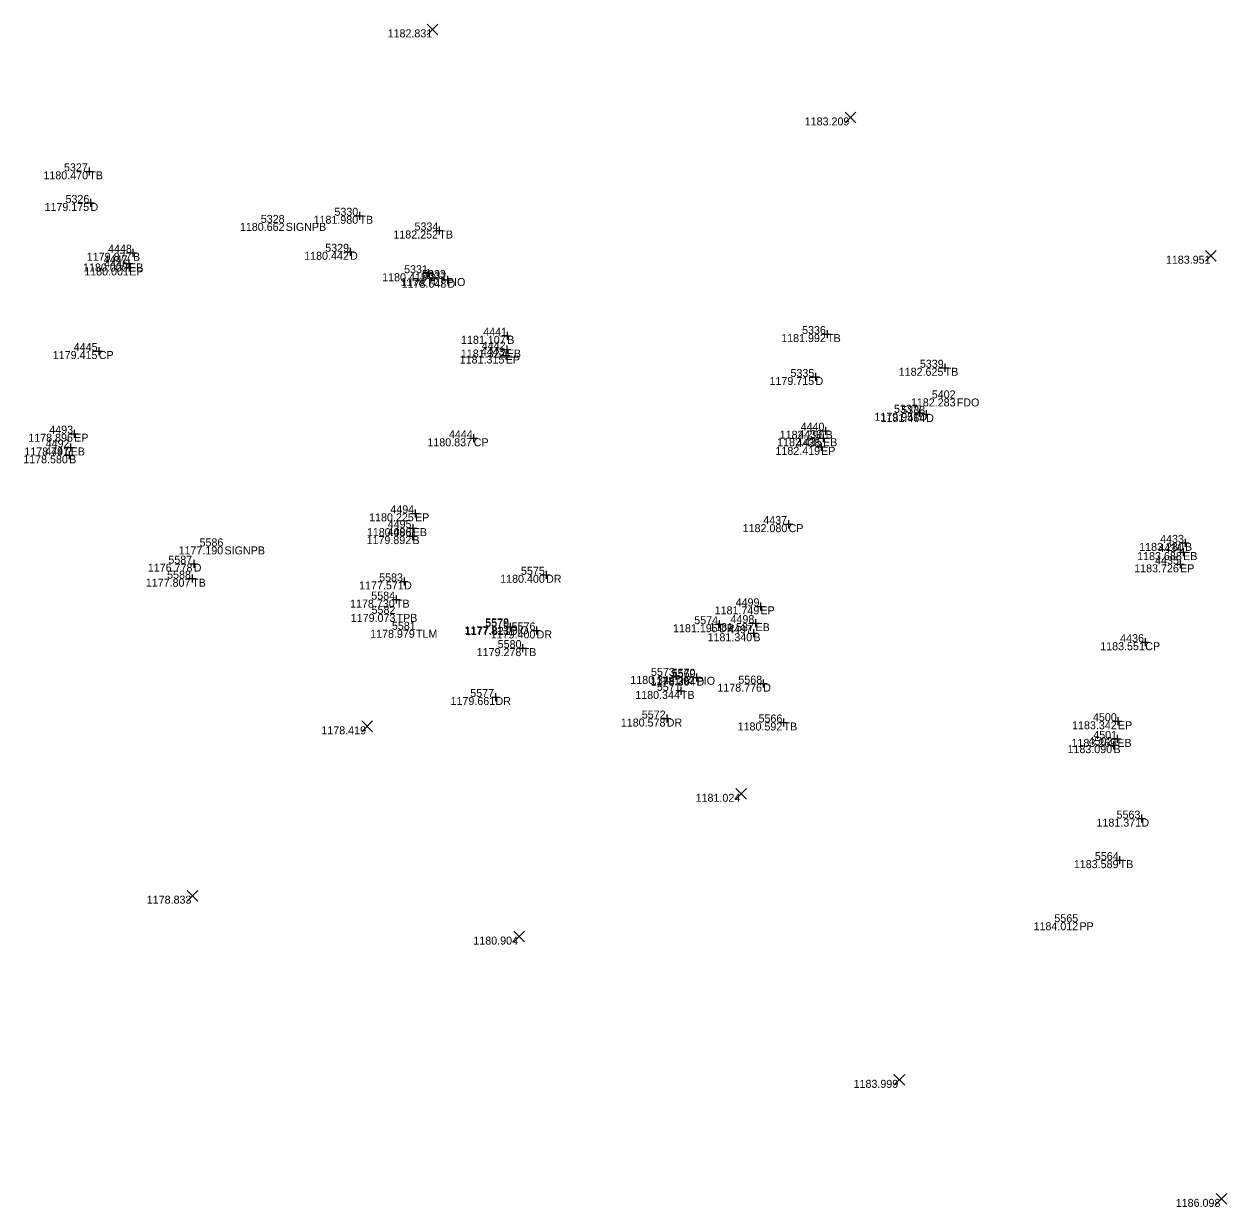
# Model space of a CAD drawing. Extents: x 2044997 to 2050342, y 455233 to 458054.
# Drawn here: x 2046906.2 to 2047056.5, y 457146.9 to 457294.7 of the extents above; entities that cross this region are included whole.
import ezdxf

# ---------------------------------------------------------------- set-up
doc = ezdxf.new("R2010")
doc.units = 0
for name, color, linetype in [('SV_X_Random_Point', 7, 'Continuous'), ('SV_X_Shot_Marker', 7, 'Continuous'), ('SV_X_Text_Comment', 7, 'Continuous'), ('SV_X_Text_Elevation', 7, 'Continuous'), ('SV_X_Text_Name', 7, 'Continuous')]:
    doc.layers.add(name, color=color, linetype=linetype)

msp = doc.modelspace()

# ---------------------------------------------------------------- linework, layer by layer
at = {"layer": 'SV_X_Random_Point'}
for p, q in [((2046956.58, 457293.4), (2046957.92, 457294.74)), ((2046956.58, 457294.74), (2046957.92, 457293.4)), ((2047008.79, 457282.4), (2047010.12, 457283.74)), ((2047008.79, 457283.74), (2047010.12, 457282.4)), ((2047053.8, 457265.12), (2047055.13, 457266.46)), ((2047053.8, 457266.46), (2047055.13, 457265.12)), ((2046948.42, 457206.32), (2046949.75, 457207.66)), ((2046948.42, 457207.66), (2046949.75, 457206.32)), ((2046995.15, 457197.89), (2046996.48, 457199.22)), ((2046995.15, 457199.22), (2046996.48, 457197.89)), ((2046926.62, 457185.16), (2046927.95, 457186.49)), ((2046926.62, 457186.49), (2046927.95, 457185.16)), ((2046967.39, 457180.05), (2046968.72, 457181.39)), ((2046967.39, 457181.39), (2046968.72, 457180.05)), ((2047014.89, 457162.15), (2047016.23, 457163.48)), ((2047014.89, 457163.48), (2047016.23, 457162.15)), ((2047055.14, 457147.28), (2047056.48, 457148.62)), ((2047055.14, 457148.62), (2047056.48, 457147.28))]:
    msp.add_line(p, q, dxfattribs=at)
at = {"layer": 'SV_X_Shot_Marker'}
for p, q in [((2046913.88, 457276.33), (2046914.88, 457276.33)), ((2046914.38, 457276.83), (2046914.38, 457275.83)), ((2046914.38, 457276.33), (2046914.38, 457276.33)), ((2046914.53, 457272.88), (2046914.53, 457271.88)), ((2046914.03, 457272.38), (2046915.03, 457272.38)), ((2046914.53, 457272.38), (2046914.53, 457272.38)), ((2046948.12, 457271.28), (2046948.12, 457270.28)), ((2046947.62, 457270.78), (2046948.62, 457270.78)), ((2046948.12, 457270.78), (2046948.12, 457270.78)), ((2046958.09, 457269.44), (2046958.09, 457268.44)), ((2046957.59, 457268.94), (2046958.59, 457268.94)), ((2046958.09, 457268.94), (2046958.09, 457268.94)), ((2046919.84, 457266.66), (2046919.84, 457265.66)), ((2046946.95, 457266.78), (2046946.95, 457265.78)), ((2046919.34, 457266.16), (2046920.34, 457266.16)), ((2046919.34, 457265.32), (2046919.34, 457264.32)), ((2046919.84, 457266.16), (2046919.84, 457266.16)), ((2046946.45, 457266.28), (2046947.45, 457266.28)), ((2046946.95, 457266.28), (2046946.95, 457266.28)), ((2046918.84, 457264.82), (2046919.84, 457264.82)), ((2046918.86, 457264.32), (2046919.86, 457264.32)), ((2046919.34, 457264.82), (2046919.34, 457264.82)), ((2046919.36, 457264.82), (2046919.36, 457263.82)), ((2046919.36, 457264.32), (2046919.36, 457264.32)), ((2046956.2, 457263.6), (2046957.2, 457263.6)), ((2046956.7, 457264.1), (2046956.7, 457263.1)), ((2046956.7, 457263.6), (2046956.7, 457263.6)), ((2046958.62, 457262.79), (2046959.62, 457262.79)), ((2046959.12, 457263.29), (2046959.12, 457262.29)), ((2046959.12, 457262.79), (2046959.12, 457262.79)), ((2046966.58, 457256.28), (2046966.58, 457255.28)), ((2047006.03, 457256), (2047007.03, 457256)), ((2047006.53, 457256.5), (2047006.53, 457255.5)), ((2047006.53, 457256), (2047006.53, 457256)), ((2046966.08, 457255.78), (2046967.08, 457255.78)), ((2046966.52, 457254.57), (2046966.52, 457253.57)), ((2046966.58, 457255.78), (2046966.58, 457255.78)), ((2046915.07, 457253.88), (2046916.07, 457253.88)), ((2046915.57, 457254.38), (2046915.57, 457253.38)), ((2046915.57, 457253.88), (2046915.57, 457253.88)), ((2046965.89, 457253.32), (2046966.89, 457253.32)), ((2046966.02, 457254.07), (2046967.02, 457254.07)), ((2046966.39, 457253.82), (2046966.39, 457252.82)), ((2046966.39, 457253.32), (2046966.39, 457253.32)), ((2046966.52, 457254.07), (2046966.52, 457254.07)), ((2047020.72, 457251.79), (2047021.72, 457251.79)), ((2047021.22, 457252.29), (2047021.22, 457251.29)), ((2047021.22, 457251.79), (2047021.22, 457251.79)), ((2047004.59, 457250.64), (2047005.59, 457250.64)), ((2047005.09, 457251.14), (2047005.09, 457250.14)), ((2047005.09, 457250.64), (2047005.09, 457250.64)), ((2047017.55, 457246.16), (2047018.55, 457246.16)), ((2047018.05, 457246.66), (2047018.05, 457245.66)), ((2047018.05, 457246.16), (2047018.05, 457246.16)), ((2047018.41, 457246.01), (2047019.41, 457246.01)), ((2047018.91, 457246.51), (2047018.91, 457245.51)), ((2047018.91, 457246.01), (2047018.91, 457246.01)), ((2046912.49, 457244.05), (2046912.49, 457243.05)), ((2047005.85, 457243.93), (2047006.85, 457243.93)), ((2047006.35, 457244.43), (2047006.35, 457243.43)), ((2047006.35, 457243.93), (2047006.35, 457243.93)), ((2046911.99, 457243.55), (2046912.99, 457243.55)), ((2046912.49, 457243.55), (2046912.49, 457243.55)), ((2046961.89, 457242.98), (2046962.89, 457242.98)), ((2046962.39, 457243.48), (2046962.39, 457242.48)), ((2046962.39, 457242.98), (2046962.39, 457242.98)), ((2047005.53, 457242.99), (2047006.53, 457242.99)), ((2047005.79, 457242.41), (2047005.79, 457241.41)), ((2047006.03, 457243.49), (2047006.03, 457242.49)), ((2047006.03, 457242.99), (2047006.03, 457242.99)), ((2046911.55, 457241.83), (2046912.55, 457241.83)), ((2046911.87, 457241.35), (2046911.87, 457240.35)), ((2046912.05, 457242.33), (2046912.05, 457241.33)), ((2046912.05, 457241.83), (2046912.05, 457241.83)), ((2047005.29, 457241.91), (2047006.29, 457241.91)), ((2047005.79, 457241.91), (2047005.79, 457241.91)), ((2046911.37, 457240.85), (2046912.37, 457240.85)), ((2046911.87, 457240.85), (2046911.87, 457240.85)), ((2046954.57, 457233.6), (2046955.57, 457233.6)), ((2046955.07, 457234.1), (2046955.07, 457233.1)), ((2046955.07, 457233.6), (2046955.07, 457233.6)), ((2046954.78, 457232.25), (2046954.78, 457231.25)), ((2047001.22, 457232.25), (2047002.22, 457232.25)), ((2047001.72, 457232.75), (2047001.72, 457231.75)), ((2047001.72, 457232.25), (2047001.72, 457232.25)), ((2046954.24, 457230.76), (2046955.24, 457230.76)), ((2046954.28, 457231.75), (2046955.28, 457231.75)), ((2046954.74, 457231.26), (2046954.74, 457230.26)), ((2046954.74, 457230.76), (2046954.74, 457230.76)), ((2046954.78, 457231.75), (2046954.78, 457231.75)), ((2047051.24, 457230.41), (2047051.24, 457229.41)), ((2047050.74, 457229.91), (2047051.74, 457229.91)), ((2047051, 457229.26), (2047051, 457228.26)), ((2047051.24, 457229.91), (2047051.24, 457229.91)), ((2046927.42, 457227.81), (2046927.42, 457226.81)), ((2047050.5, 457228.76), (2047051.5, 457228.76)), ((2047050.63, 457227.73), (2047050.63, 457226.73)), ((2047051, 457228.76), (2047051, 457228.76)), ((2046926.92, 457227.31), (2046927.92, 457227.31)), ((2046927.22, 457225.94), (2046927.22, 457224.94)), ((2046927.42, 457227.31), (2046927.42, 457227.31)), ((2046970.93, 457225.92), (2046971.93, 457225.92)), ((2046971.43, 457226.42), (2046971.43, 457225.42)), ((2046971.43, 457225.92), (2046971.43, 457225.92)), ((2047050.13, 457227.23), (2047051.13, 457227.23)), ((2047050.63, 457227.23), (2047050.63, 457227.23)), ((2046926.72, 457225.44), (2046927.72, 457225.44)), ((2046927.22, 457225.44), (2046927.22, 457225.44)), ((2046953.19, 457225.1), (2046954.19, 457225.1)), ((2046953.69, 457225.6), (2046953.69, 457224.6)), ((2046953.69, 457225.1), (2046953.69, 457225.1)), ((2046952.69, 457223.32), (2046952.69, 457222.32)), ((2046952.19, 457222.82), (2046953.19, 457222.82)), ((2046952.69, 457222.82), (2046952.69, 457222.82)), ((2046997.71, 457221.98), (2046998.71, 457221.98)), ((2046998.21, 457222.48), (2046998.21, 457221.48)), ((2046998.21, 457221.98), (2046998.21, 457221.98)), ((2046966.93, 457219.9), (2046966.93, 457218.9)), ((2046993.04, 457220.25), (2046993.04, 457219.25)), ((2046997.09, 457219.88), (2046998.09, 457219.88)), ((2046997.59, 457220.38), (2046997.59, 457219.38)), ((2046997.59, 457219.88), (2046997.59, 457219.88)), ((2046966.43, 457219.4), (2046967.43, 457219.4)), ((2046966.93, 457219.4), (2046966.93, 457219.4)), ((2046969.75, 457218.97), (2046970.75, 457218.97)), ((2046970.25, 457219.47), (2046970.25, 457218.47)), ((2046970.25, 457218.97), (2046970.25, 457218.97)), ((2046992.54, 457219.75), (2046993.54, 457219.75)), ((2046993.04, 457219.75), (2046993.04, 457219.75)), ((2046996.83, 457218.62), (2046997.83, 457218.62)), ((2046997.33, 457219.12), (2046997.33, 457218.12)), ((2046997.33, 457218.62), (2046997.33, 457218.62)), ((2046968.51, 457217.26), (2046968.51, 457216.26)), ((2047045.77, 457217.5), (2047046.77, 457217.5)), ((2047046.27, 457218), (2047046.27, 457217)), ((2047046.27, 457217.5), (2047046.27, 457217.5)), ((2046968.01, 457216.76), (2046969.01, 457216.76)), ((2046968.51, 457216.76), (2046968.51, 457216.76)), ((2046987.15, 457213.29), (2046988.15, 457213.29)), ((2046987.65, 457213.79), (2046987.65, 457212.79)), ((2046987.65, 457213.29), (2046987.65, 457213.29)), ((2046989.72, 457213.07), (2046990.72, 457213.07)), ((2046990.22, 457213.57), (2046990.22, 457212.57)), ((2046990.22, 457213.07), (2046990.22, 457213.07)), ((2046998.56, 457212.82), (2046998.56, 457211.82)), ((2046965.12, 457211.15), (2046965.12, 457210.15)), ((2046987.77, 457211.41), (2046988.77, 457211.41)), ((2046988.27, 457211.91), (2046988.27, 457210.91)), ((2046988.27, 457211.41), (2046988.27, 457211.41)), ((2046998.06, 457212.32), (2046999.06, 457212.32)), ((2046998.56, 457212.32), (2046998.56, 457212.32)), ((2046964.62, 457210.65), (2046965.62, 457210.65)), ((2046965.12, 457210.65), (2046965.12, 457210.65)), ((2046986, 457207.96), (2046987, 457207.96)), ((2046986.5, 457208.46), (2046986.5, 457207.46)), ((2046986.5, 457207.96), (2046986.5, 457207.96)), ((2047001.09, 457207.97), (2047001.09, 457206.97)), ((2047042.86, 457208.12), (2047042.86, 457207.12)), ((2047000.59, 457207.47), (2047001.59, 457207.47)), ((2047001.09, 457207.47), (2047001.09, 457207.47)), ((2047042.36, 457207.62), (2047043.36, 457207.62)), ((2047042.86, 457207.62), (2047042.86, 457207.62)), ((2047042.28, 457205.42), (2047043.28, 457205.42)), ((2047042.3, 457205.14), (2047042.3, 457204.14)), ((2047042.78, 457205.92), (2047042.78, 457204.92)), ((2047042.78, 457205.42), (2047042.78, 457205.42)), ((2047041.8, 457204.64), (2047042.8, 457204.64)), ((2047042.3, 457204.64), (2047042.3, 457204.64)), ((2047045.79, 457195.96), (2047045.79, 457194.96)), ((2047045.29, 457195.46), (2047046.29, 457195.46)), ((2047045.79, 457195.46), (2047045.79, 457195.46)), ((2047042.57, 457190.27), (2047043.57, 457190.27)), ((2047043.07, 457190.77), (2047043.07, 457189.77)), ((2047043.07, 457190.27), (2047043.07, 457190.27))]:
    msp.add_line(p, q, dxfattribs=at)

# ---------------------------------------------------------------- texts
at = {"layer": 'SV_X_Text_Comment'}
for s, p in [('TB', (2046914.38, 457275.33)), ('D', (2046914.53, 457271.38)), ('SIGNPB', (2046938.92, 457268.89)), ('TB', (2046948.12, 457269.78)), ('TB', (2046958.09, 457267.94)), ('B', (2046919.84, 457265.16)), ('D', (2046946.95, 457265.28)), ('EB', (2046919.34, 457263.82)), ('EP', (2046919.36, 457263.32)), ('D', (2046956.7, 457262.6)), ('PIO', (2046959.05, 457262)), ('D', (2046959.12, 457261.79)), ('TB', (2047006.53, 457255)), ('B', (2046966.58, 457254.78)), ('CP', (2046915.57, 457252.88)), ('EP', (2046966.39, 457252.32)), ('EB', (2046966.52, 457253.07)), ('TB', (2047021.22, 457250.79)), ('D', (2047005.09, 457249.64)), ('FDO', (2047022.73, 457246.96)), ('D', (2047018.05, 457245.16)), ('D', (2047018.91, 457245.01)), ('B', (2047006.35, 457242.93)), ('EP', (2046912.49, 457242.55)), ('CP', (2046962.39, 457241.98)), ('EB', (2047006.03, 457241.99)), ('EB', (2046912.05, 457240.83)), ('EP', (2047005.79, 457240.91)), ('B', (2046911.87, 457239.85)), ('EP', (2046955.07, 457232.6)), ('CP', (2047001.72, 457231.25)), ('B', (2046954.74, 457229.76)), ('EB', (2046954.78, 457230.75)), ('SIGNPB', (2046931.27, 457228.47)), ('B', (2047051.24, 457228.91)), ('EB', (2047051, 457227.76)), ('D', (2046927.42, 457226.31)), ('DR', (2046971.43, 457224.92)), ('EP', (2047050.63, 457226.23)), ('TB', (2046927.22, 457224.44)), ('D', (2046953.69, 457224.1)), ('TB', (2046952.69, 457221.82)), ('EP', (2046998.21, 457220.98)), ('TPB', (2046952.76, 457220.04)), ('EB', (2046997.59, 457218.88)), ('TLM', (2046955.18, 457218.05)), ('D', (2046966.93, 457218.4)), ('PIO', (2046966.95, 457218.48)), ('DR', (2046970.25, 457217.97)), ('DR', (2046993.04, 457218.75)), ('B', (2046997.33, 457217.62)), ('CP', (2047046.27, 457216.5)), ('TB', (2046968.51, 457215.76)), ('DR', (2046987.65, 457212.29)), ('D', (2046990.22, 457212.07)), ('PIO', (2046990.24, 457212.18)), ('TB', (2046988.27, 457210.41)), ('D', (2046998.56, 457211.32)), ('DR', (2046965.12, 457209.65)), ('DR', (2046986.5, 457206.96)), ('TB', (2047001.09, 457206.47)), ('EP', (2047042.86, 457206.62)), ('EB', (2047042.78, 457204.42)), ('B', (2047042.3, 457203.64)), ('D', (2047045.79, 457194.46)), ('TB', (2047043.07, 457189.27)), ('PP', (2047038.05, 457181.51))]:
    msp.add_text(s, height=1, dxfattribs=at).set_placement(p)
at = {"layer": 'SV_X_Text_Elevation'}
for s, p in [('1182.831', (2046951.64, 457293.07)), ('1183.209', (2047003.74, 457282.07)), ('1180.470', (2046908.65, 457275.33)), ('1179.175', (2046908.79, 457271.38)), ('1180.662', (2046933.19, 457268.89)), ('1181.980', (2046942.39, 457269.78)), ('1182.252', (2046952.36, 457267.94)), ('1179.877', (2046914.07, 457265.16)), ('1180.442', (2046941.22, 457265.28)), ('1183.951', (2047048.85, 457264.79)), ('1180.000', (2046913.6, 457263.82)), ('1180.001', (2046913.75, 457263.32)), ('1180.415', (2046950.96, 457262.6)), ('1178.707', (2046953.27, 457262)), ('1178.648', (2046953.39, 457261.79)), ('1181.992', (2047000.8, 457255)), ('1181.107', (2046960.81, 457254.78)), ('1179.415', (2046909.82, 457252.88)), ('1181.315', (2046960.65, 457252.32)), ('1181.322', (2046960.79, 457253.07)), ('1182.625', (2047015.48, 457250.79)), ('1179.715', (2046999.34, 457249.64)), ('1182.283', (2047017, 457246.96)), ('1179.951', (2047012.44, 457245.16)), ('1181.464', (2047013.21, 457245.01)), ('1182.290', (2047000.61, 457242.93)), ('1178.896', (2046906.76, 457242.55)), ('1180.837', (2046956.61, 457241.98)), ('1182.435', (2047000.29, 457241.99)), ('1178.747', (2046906.27, 457240.83)), ('1182.419', (2047000.08, 457240.91)), ('1178.580', (2046906.13, 457239.85)), ('1180.225', (2046949.33, 457232.6)), ('1182.080', (2046995.99, 457231.25)), ('1179.892', (2046949.01, 457229.76)), ('1180.088', (2046949.05, 457230.75)), ('1177.190', (2046925.53, 457228.47)), ('1183.280', (2047045.51, 457228.91)), ('1183.688', (2047045.26, 457227.76)), ('1176.778', (2046921.69, 457226.31)), ('1180.400', (2046965.7, 457224.92)), ('1183.726', (2047044.89, 457226.23)), ('1177.807', (2046921.44, 457224.44)), ('1177.571', (2046948.08, 457224.1)), ('1178.730', (2046946.95, 457221.82)), ('1181.749', (2046992.49, 457220.98)), ('1179.073', (2046947.04, 457220.04)), ('1181.587', (2046991.81, 457218.88)), ('1178.979', (2046949.46, 457218.05)), ('1177.813', (2046961.23, 457218.48)), ('1177.821', (2046961.32, 457218.4)), ('1179.400', (2046964.52, 457217.97)), ('1181.195', (2046987.29, 457218.75)), ('1181.340', (2046991.6, 457217.62)), ('1183.551', (2047040.65, 457216.5)), ('1179.278', (2046962.77, 457215.76)), ('1180.344', (2046981.95, 457212.29)), ('1178.297', (2046984.46, 457212.18)), ('1178.304', (2046984.52, 457212.07)), ('1180.344', (2046982.57, 457210.41)), ('1178.776', (2046992.83, 457211.32)), ('1179.661', (2046959.5, 457209.65)), ('1180.578', (2046980.77, 457206.96)), ('1178.419', (2046943.37, 457205.99)), ('1180.592', (2046995.36, 457206.47)), ('1183.342', (2047037.13, 457206.62)), ('1183.269', (2047037.06, 457204.42)), ('1183.090', (2047036.56, 457203.64)), ('1181.024', (2046990.11, 457197.56)), ('1181.371', (2047040.18, 457194.46)), ('1183.589', (2047037.35, 457189.27)), ('1178.833', (2046921.56, 457184.83)), ('1184.012', (2047032.32, 457181.51)), ('1180.904', (2046962.35, 457179.72)), ('1183.999', (2047009.84, 457161.82)), ('1186.098', (2047050.08, 457146.95))]:
    msp.add_text(s, height=1, dxfattribs=at).set_placement(p)
at = {"layer": 'SV_X_Text_Name'}
for s, p in [('5327', (2046911.22, 457276.33)), ('5326', (2046911.41, 457272.38)), ('5330', (2046945, 457270.78)), ('5328', (2046935.8, 457269.89)), ('5334', (2046955, 457268.94)), ('4448', (2046916.72, 457266.16)), ('5329', (2046943.85, 457266.28)), ('4447', (2046916.18, 457264.82)), ('4446', (2046916.24, 457264.32)), ('5331', (2046953.7, 457263.6)), ('5333', (2046955.94, 457263)), ('5332', (2046956, 457262.79)), ('4441', (2046963.58, 457255.78)), ('5336', (2047003.41, 457256)), ('4445', (2046912.44, 457253.88)), ('4442', (2046963.4, 457254.07)), ('4443', (2046963.28, 457253.32)), ('5335', (2047001.96, 457250.64)), ('5339', (2047018.12, 457251.79)), ('5402', (2047019.61, 457247.96)), ('5337', (2047014.89, 457246.16)), ('5338', (2047015.8, 457246.01)), ('4493', (2046909.38, 457243.55)), ('4444', (2046959.3, 457242.98)), ('4439', (2047002.93, 457242.99)), ('4440', (2047003.23, 457243.93)), ('4492', (2046908.93, 457241.83)), ('4438', (2047002.68, 457241.91)), ('4491', (2046908.87, 457240.85)), ('4494', (2046951.98, 457233.6)), ('4495', (2046951.65, 457231.75)), ('4437', (2046998.56, 457232.25)), ('5586', (2046928.15, 457229.47)), ('4496', (2046951.62, 457230.76)), ('4433', (2047048.13, 457229.91)), ('4434', (2047047.91, 457228.76)), ('5587', (2046924.26, 457227.31)), ('4435', (2047047.5, 457227.23)), ('5588', (2046924.1, 457225.44)), ('5583', (2046950.58, 457225.1)), ('5575', (2046968.3, 457225.92)), ('5584', (2046949.6, 457222.82)), ('4499', (2046995.11, 457221.98)), ('5582', (2046949.64, 457221.04)), ('5581', (2046952.18, 457219.05)), ('5579', (2046963.83, 457219.4)), ('5578', (2046963.84, 457219.48)), ('5576', (2046967.13, 457218.97)), ('5574', (2046989.95, 457219.75)), ('4498', (2046994.47, 457219.88)), ('4497', (2046994.17, 457218.62)), ('4436', (2047043.14, 457217.5)), ('5580', (2046965.39, 457216.76)), ('5573', (2046984.54, 457213.29)), ('5570', (2046987.12, 457213.18)), ('5569', (2046987.12, 457213.07)), ('5571', (2046985.27, 457211.41)), ('5568', (2046995.45, 457212.32)), ('5577', (2046961.96, 457210.65)), ('5572', (2046983.39, 457207.96)), ('5566', (2046997.97, 457207.47)), ('4500', (2047039.74, 457207.62)), ('4501', (2047039.78, 457205.42)), ('4502', (2047039.18, 457204.64)), ('5563', (2047042.69, 457195.46)), ('5564', (2047039.98, 457190.27)), ('5565', (2047034.92, 457182.51))]:
    msp.add_text(s, height=1, dxfattribs=at).set_placement(p)

doc.saveas('drawing.dxf')
